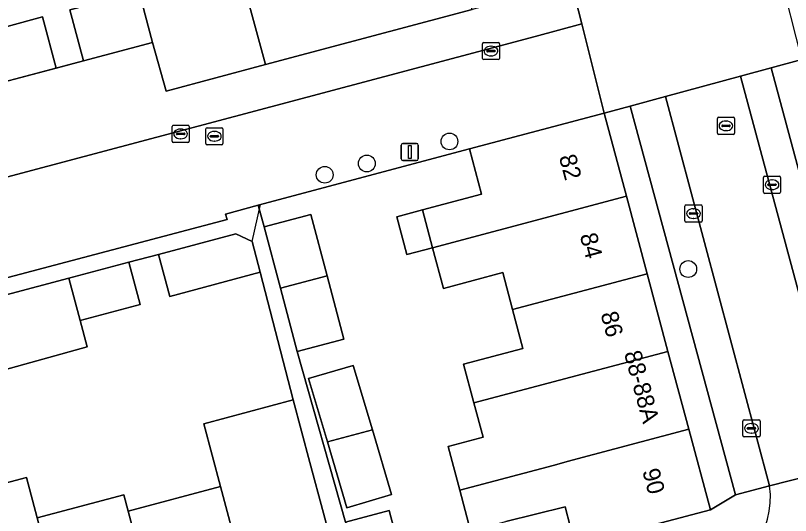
# Model space of a CAD drawing. Extents: x 162542 to 163147, y 380779 to 381521.
# Drawn here: x 162757.65 to 162802.78, y 381070.34 to 381099.45 of the extents above; entities that cross this region are included whole.
import ezdxf

# ---------------------------------------------------------------- set-up
doc = ezdxf.new("R2010")
doc.units = 0
for name, color, linetype in [('IMGEO_Boom', 7, 'Continuous'), ('IMGEO_Erf', 7, 'Continuous'), ('IMGEO_Kolk', 7, 'Continuous'), ('IMGEO_Lichtmast', 7, 'Continuous'), ('IMGEO_Muur', 7, 'Continuous'), ('IMGEO_Pand', 7, 'Continuous'), ('IMGEO_Pand_nummerreeks', 7, 'Continuous'), ('IMGEO_Parkeervlak_open', 7, 'Continuous'), ('IMGEO_Rijbaan_lokaal_open', 7, 'Continuous'), ('IMGEO_Rioolput', 7, 'Continuous'), ('IMGEO_Voetpad_open', 7, 'Continuous')]:
    doc.layers.add(name, color=color, linetype=linetype)

msp = doc.modelspace()

# ---------------------------------------------------------------- linework, layer by layer
at = {"layer": 'IMGEO_Boom'}
for centre in [(162782.921, 381092.117), (162778.113, 381090.832), (162775.658, 381090.177), (162796.83, 381084.688)]:
    msp.add_circle(centre, 0.489, dxfattribs=at)
at = {"layer": 'IMGEO_Erf'}
for points in [[(162755.09, 381098.253), (162759.227, 381099.362), (162760.023, 381096.39), (162761.612, 381096.812), (162760.816, 381099.779), (162764.843, 381100.832), (162763.436, 381106.099), (162757.913, 381104.631), (162752.088, 381103.082)], [(162784.155, 381069.446), (162783.526, 381071.816), (162782.85, 381074.362), (162784.879, 381074.9), (162784.35, 381076.893), (162783.75, 381079.151), (162787.199, 381080.067), (162786.599, 381082.327), (162786.026, 381084.483), (162782.566, 381083.564), (162781.939, 381085.926), (162780.449, 381085.53), (162779.864, 381087.732), (162781.354, 381088.128), (162784.796, 381089.042), (162784.095, 381091.679), (162771.776, 381088.409), (162772.128, 381087.14), (162774.85, 381087.863), (162775.799, 381084.295), (162776.779, 381080.611), (162774.056, 381079.887), (162776.859, 381069.965), (162779.405, 381070.644), (162780.482, 381066.606)], [(162753.086, 381071.17), (162758.292, 381072.559), (162758.919, 381070.209), (162763.957, 381071.553), (162764.213, 381070.599), (162769.584, 381072.032), (162768.611, 381075.681), (162773.82, 381077.07), (162771.904, 381084.512), (162766.629, 381083.09), (162765.973, 381085.543), (162764.247, 381085.085), (162764.909, 381082.626), (162761.423, 381081.687), (162761.823, 381080.162), (162756.645, 381078.719)], [(162790.25, 381068.607), (162789.654, 381070.857), (162786.215, 381069.993)]]:
    msp.add_lwpolyline(points, dxfattribs=at)
for points in [[(162770.633, 381102.367), (162764.843, 381100.832), (162765.622, 381097.877), (162766.422, 381095.044), (162772.214, 381096.585)], [(162778.435, 381075.322), (162779.547, 381071.566), (162776.947, 381070.796), (162775.814, 381074.626), (162774.723, 381078.31), (162777.322, 381079.08)]]:
    msp.add_lwpolyline(points, close=True, dxfattribs=at)
at = {"layer": 'IMGEO_Kolk'}
for p, q in [((162784.841, 381096.951), (162784.841, 381097.803)), ((162784.916, 381097.877), (162785.768, 381097.877)), ((162785.842, 381097.803), (162785.842, 381096.951)), ((162785.1, 381097.371), (162785.1, 381097.383)), ((162785.538, 381097.334), (162785.14, 381097.334)), ((162785.143, 381097.42), (162785.541, 381097.42)), ((162785.329, 381097.657), (162785.354, 381097.657)), ((162785.584, 381097.383), (162785.584, 381097.371)), ((162785.768, 381096.877), (162784.916, 381096.877)), ((162785.352, 381097.097), (162785.327, 381097.097)), ((162766.765, 381092.128), (162766.765, 381092.98)), ((162766.84, 381093.054), (162767.692, 381093.054)), ((162767.253, 381092.834), (162767.278, 381092.834)), ((162767.766, 381092.98), (162767.766, 381092.128)), ((162767.024, 381092.548), (162767.024, 381092.56)), ((162767.462, 381092.511), (162767.064, 381092.511)), ((162767.067, 381092.597), (162767.465, 381092.597)), ((162767.508, 381092.56), (162767.508, 381092.548)), ((162767.692, 381092.054), (162766.84, 381092.054)), ((162767.276, 381092.274), (162767.251, 381092.274)), ((162801.283, 381090.095), (162802.135, 381090.095)), ((162801.208, 381089.169), (162801.208, 381090.021)), ((162801.51, 381089.638), (162801.908, 381089.638)), ((162801.696, 381089.875), (162801.721, 381089.875)), ((162802.209, 381090.021), (162802.209, 381089.169)), ((162801.467, 381089.589), (162801.467, 381089.601)), ((162801.905, 381089.552), (162801.507, 381089.552)), ((162801.719, 381089.315), (162801.694, 381089.315)), ((162801.951, 381089.601), (162801.951, 381089.589)), ((162802.135, 381089.095), (162801.283, 381089.095)), ((162796.635, 381087.492), (162796.635, 381088.344)), ((162796.71, 381088.418), (162797.562, 381088.418)), ((162797.636, 381088.344), (162797.636, 381087.492)), ((162796.894, 381087.912), (162796.894, 381087.924)), ((162797.332, 381087.875), (162796.934, 381087.875)), ((162796.937, 381087.961), (162797.335, 381087.961)), ((162797.123, 381088.198), (162797.148, 381088.198)), ((162797.378, 381087.924), (162797.378, 381087.912)), ((162797.562, 381087.418), (162796.71, 381087.418)), ((162797.146, 381087.638), (162797.121, 381087.638)), ((162800.01, 381074.992), (162800.01, 381075.844)), ((162800.085, 381075.918), (162800.937, 381075.918)), ((162800.498, 381075.698), (162800.523, 381075.698)), ((162801.011, 381075.844), (162801.011, 381074.992)), ((162800.269, 381075.412), (162800.269, 381075.424)), ((162800.707, 381075.375), (162800.309, 381075.375)), ((162800.312, 381075.461), (162800.71, 381075.461)), ((162800.753, 381075.424), (162800.753, 381075.412)), ((162800.937, 381074.918), (162800.085, 381074.918)), ((162800.521, 381075.138), (162800.496, 381075.138))]:
    msp.add_line(p, q, dxfattribs=at)
for points in [[(162784.841, 381096.951), (162784.841, 381097.803)], [(162784.916, 381097.877), (162785.768, 381097.877)], [(162785.842, 381097.803), (162785.842, 381096.951)], [(162785.768, 381096.877), (162784.916, 381096.877)], [(162766.765, 381092.128), (162766.765, 381092.98)], [(162766.84, 381093.054), (162767.692, 381093.054)], [(162767.766, 381092.98), (162767.766, 381092.128)], [(162767.692, 381092.054), (162766.84, 381092.054)], [(162801.283, 381090.095), (162802.135, 381090.095)], [(162801.208, 381089.169), (162801.208, 381090.021)], [(162802.209, 381090.021), (162802.209, 381089.169)], [(162802.135, 381089.095), (162801.283, 381089.095)], [(162796.635, 381087.492), (162796.635, 381088.344)], [(162796.71, 381088.418), (162797.562, 381088.418)], [(162797.636, 381088.344), (162797.636, 381087.492)], [(162797.562, 381087.418), (162796.71, 381087.418)], [(162800.01, 381074.992), (162800.01, 381075.844)], [(162800.085, 381075.918), (162800.937, 381075.918)], [(162801.011, 381075.844), (162801.011, 381074.992)], [(162800.937, 381074.918), (162800.085, 381074.918)]]:
    msp.add_lwpolyline(points, dxfattribs=at)
for centre, radius, start, end in [((162784.918, 381097.801), 0.0765, 91.552, 178.448), ((162784.918, 381097.801), 0.0765, 91.552, 178.448), ((162785.766, 381097.801), 0.0765, 1.552, 88.448), ((162785.766, 381097.801), 0.0765, 1.552, 88.448), ((162785.14, 381097.38), 0.0403, 85.8775, 175.7526), ((162785.137, 381097.37), 0.0366, 178.938, 274.7102), ((162785.541, 381097.377), 0.043, 264.8664, 352.4533), ((162785.545, 381097.382), 0.0386, 1.7309, 96.639), ((162784.918, 381096.953), 0.0765, 181.552, 268.448), ((162784.918, 381096.953), 0.0765, 181.552, 268.448), ((162785.766, 381096.953), 0.0765, 271.552, 358.448), ((162785.766, 381096.953), 0.0765, 271.552, 358.448), ((162766.842, 381092.978), 0.0765, 91.552, 178.448), ((162766.842, 381092.978), 0.0765, 91.552, 178.448), ((162767.69, 381092.978), 0.0765, 1.552, 88.448), ((162767.69, 381092.978), 0.0765, 1.552, 88.448), ((162767.064, 381092.557), 0.0403, 85.8775, 175.7526), ((162767.061, 381092.547), 0.0366, 178.938, 274.7102), ((162767.465, 381092.554), 0.043, 264.8664, 352.4533), ((162767.469, 381092.559), 0.0386, 1.7309, 96.639), ((162766.842, 381092.13), 0.0765, 181.552, 268.448), ((162766.842, 381092.13), 0.0765, 181.552, 268.448), ((162767.69, 381092.13), 0.0765, 271.552, 358.448), ((162767.69, 381092.13), 0.0765, 271.552, 358.448), ((162801.285, 381090.019), 0.0765, 91.552, 178.448), ((162801.285, 381090.019), 0.0765, 91.552, 178.448), ((162802.133, 381090.019), 0.0765, 1.552, 88.448), ((162802.133, 381090.019), 0.0765, 1.552, 88.448), ((162801.507, 381089.598), 0.0403, 85.8775, 175.7526), ((162801.912, 381089.6), 0.0386, 1.7309, 96.639), ((162801.504, 381089.588), 0.0366, 178.938, 274.7102), ((162801.908, 381089.595), 0.043, 264.8664, 352.4533), ((162801.285, 381089.171), 0.0765, 181.552, 268.448), ((162801.285, 381089.171), 0.0765, 181.552, 268.448), ((162802.133, 381089.171), 0.0765, 271.552, 358.448), ((162802.133, 381089.171), 0.0765, 271.552, 358.448), ((162796.712, 381088.342), 0.0765, 91.552, 178.448), ((162796.712, 381088.342), 0.0765, 91.552, 178.448), ((162797.56, 381088.342), 0.0765, 1.552, 88.448), ((162797.56, 381088.342), 0.0765, 1.552, 88.448), ((162796.934, 381087.921), 0.0403, 85.8775, 175.7526), ((162796.931, 381087.911), 0.0366, 178.938, 274.7102), ((162797.335, 381087.918), 0.043, 264.8664, 352.4533), ((162797.339, 381087.923), 0.0386, 1.7309, 96.639), ((162796.712, 381087.494), 0.0765, 181.552, 268.448), ((162796.712, 381087.494), 0.0765, 181.552, 268.448), ((162797.56, 381087.494), 0.0765, 271.552, 358.448), ((162797.56, 381087.494), 0.0765, 271.552, 358.448), ((162800.087, 381075.842), 0.0765, 91.552, 178.448), ((162800.087, 381075.842), 0.0765, 91.552, 178.448), ((162800.935, 381075.842), 0.0765, 1.552, 88.448), ((162800.935, 381075.842), 0.0765, 1.552, 88.448), ((162800.309, 381075.421), 0.0403, 85.8775, 175.7526), ((162800.306, 381075.411), 0.0366, 178.938, 274.7102), ((162800.71, 381075.418), 0.043, 264.8664, 352.4533), ((162800.714, 381075.423), 0.0386, 1.7309, 96.639), ((162800.087, 381074.994), 0.0765, 181.552, 268.448), ((162800.087, 381074.994), 0.0765, 181.552, 268.448), ((162800.935, 381074.994), 0.0765, 271.552, 358.448), ((162800.935, 381074.994), 0.0765, 271.552, 358.448)]:
    msp.add_arc(centre, radius, start, end, dxfattribs=at)
for centre, major_axis, ratio, start_param, end_param in [((162785.328, 381097.377), (-0.387, 0.002), 0.722429, 4.712389, 7.853982), ((162785.353, 381097.377), (-0.39, 0.002), 0.717154, 1.570796, 4.712389), ((162767.252, 381092.554), (-0.387, 0.002), 0.722429, 4.712389, 7.853982), ((162767.277, 381092.554), (-0.39, 0.002), 0.717154, 1.570796, 4.712389), ((162801.695, 381089.595), (-0.387, 0.002), 0.722429, 4.712389, 7.853982), ((162801.72, 381089.595), (-0.39, 0.002), 0.717154, 1.570796, 4.712389), ((162797.122, 381087.918), (-0.387, 0.002), 0.722429, 4.712389, 7.853982), ((162797.147, 381087.918), (-0.39, 0.002), 0.717154, 1.570796, 4.712389), ((162800.497, 381075.418), (-0.387, 0.002), 0.722429, 4.712389, 7.853982), ((162800.522, 381075.418), (-0.39, 0.002), 0.717154, 1.570796, 4.712389)]:
    msp.add_ellipse(centre, major_axis=major_axis, ratio=ratio, start_param=start_param, end_param=end_param, dxfattribs=at)
at = {"layer": 'IMGEO_Lichtmast'}
for p, q in [((162780.113, 381091.106), (162780.113, 381091.906)), ((162780.113, 381091.906), (162780.113, 381091.106)), ((162780.213, 381092.006), (162781.003, 381092.006)), ((162781.003, 381092.006), (162780.213, 381092.006)), ((162781.103, 381091.906), (162781.103, 381091.106)), ((162781.103, 381091.106), (162781.103, 381091.906)), ((162781.003, 381091.006), (162780.213, 381091.006)), ((162780.213, 381091.006), (162781.003, 381091.006))]:
    msp.add_line(p, q, dxfattribs=at)
msp.add_lwpolyline([(162780.533, 381091.881), (162780.683, 381091.881), (162780.683, 381091.131), (162780.533, 381091.131), (162780.533, 381091.881)], dxfattribs=at)
for centre, start, end in [((162780.213, 381091.906), 90, 180), ((162780.213, 381091.906), 90, 180), ((162781.003, 381091.906), 0, 90), ((162781.003, 381091.906), 360, 90), ((162780.213, 381091.106), 180, 270), ((162780.213, 381091.106), 180, 270), ((162781.003, 381091.106), 270, 0), ((162781.003, 381091.106), 270, 0)]:
    msp.add_arc(centre, 0.1, start, end, dxfattribs=at)
at = {"layer": 'IMGEO_Muur'}
for points in [[(162772.214, 381096.585), (162766.422, 381095.044), (162765.622, 381097.877), (162701.846, 381080.936)], [(162771.921, 381088.449), (162784.095, 381091.679)], [(162771.43, 381086.295), (162771.921, 381088.449)]]:
    msp.add_lwpolyline(points, dxfattribs=at)
at = {"layer": 'IMGEO_Pand'}
for points in [[(162763.436, 381106.099), (162764.843, 381100.832), (162770.633, 381102.367), (162772.214, 381096.585), (162784.24, 381099.787), (162782.711, 381105.584), (162788.487, 381107.117), (162785.291, 381119.142), (162779.493, 381117.608), (162777.951, 381123.405), (162765.901, 381120.189), (162767.441, 381114.419), (162761.884, 381112.936)], [(162764.843, 381100.832), (162760.816, 381099.779), (162761.612, 381096.812), (162765.622, 381097.877)], [(162759.227, 381099.362), (162755.09, 381098.253), (162755.884, 381095.29), (162760.023, 381096.39)], [(162793.225, 381088.924), (162791.929, 381093.758), (162784.095, 381091.679), (162784.796, 381089.042), (162781.354, 381088.128), (162781.939, 381085.926)], [(162794.436, 381084.409), (162793.225, 381088.924), (162781.939, 381085.926), (162782.566, 381083.564), (162786.026, 381084.483), (162786.599, 381082.327)], [(162772.128, 381087.14), (162773.076, 381083.572), (162775.799, 381084.295), (162774.85, 381087.863)], [(162781.354, 381088.128), (162779.864, 381087.732), (162780.449, 381085.53), (162781.939, 381085.926)], [(162765.973, 381085.543), (162766.629, 381083.09), (162771.904, 381084.512), (162771.43, 381086.295), (162770.479, 381086.739)], [(162764.247, 381085.085), (162760.765, 381084.161), (162761.423, 381081.687), (162764.909, 381082.626)], [(162775.799, 381084.295), (162773.076, 381083.572), (162774.056, 381079.887), (162776.779, 381080.611)], [(162795.646, 381079.894), (162794.436, 381084.409), (162786.599, 381082.327), (162787.199, 381080.067), (162783.75, 381079.151), (162784.35, 381076.893)], [(162755.559, 381082.78), (162756.645, 381078.719), (162761.823, 381080.162), (162761.423, 381081.687), (162760.765, 381084.161)], [(162795.646, 381079.894), (162784.35, 381076.893), (162784.879, 381074.9), (162782.85, 381074.362), (162783.526, 381071.816), (162788.962, 381073.26), (162789.181, 381073.318), (162789.775, 381073.478), (162796.857, 381075.377)], [(162775.814, 381074.626), (162778.435, 381075.322), (162777.322, 381079.08), (162774.723, 381078.31)], [(162771.805, 381063.723), (162774.182, 381064.357), (162774.346, 381064.969), (162776.867, 381065.641), (162775.579, 381070.473), (162774.793, 381073.421), (162773.82, 381077.07), (162768.611, 381075.681), (162769.584, 381072.032)], [(162775.814, 381074.626), (162776.947, 381070.796), (162779.547, 381071.566), (162778.435, 381075.322)], [(162796.857, 381075.377), (162789.775, 381073.478), (162789.181, 381073.318), (162788.962, 381073.26), (162783.526, 381071.816), (162784.155, 381069.446), (162786.215, 381069.993), (162789.654, 381070.857), (162790.25, 381068.607), (162798.117, 381070.679)], [(162753.086, 381071.17), (162755.78, 381061.091), (162758.026, 381061.69), (162758.49, 381061.225), (162761.132, 381061.93), (162758.919, 381070.209), (162758.292, 381072.559)], [(162769.584, 381072.032), (162764.213, 381070.599), (162766.025, 381063.843), (162765.878, 381063.804), (162766.136, 381062.838), (162768.598, 381063.494), (162769.091, 381063), (162771.805, 381063.723)], [(162764.213, 381070.599), (162763.957, 381071.553), (162758.919, 381070.209), (162761.132, 381061.93), (162763.577, 381062.582), (162763.754, 381063.237), (162765.878, 381063.804), (162766.025, 381063.843)], [(162780.482, 381066.606), (162779.405, 381070.644), (162776.859, 381069.965), (162777.935, 381065.927)]]:
    msp.add_lwpolyline(points, close=True, dxfattribs=at)
at = {"layer": 'IMGEO_Parkeervlak_open'}
for points in [[(162801.665, 381096.397), (162799.877, 381095.912), (162805.992, 381073.201), (162807.774, 381073.68)], [(162795.495, 381094.724), (162793.451, 381094.17), (162799.581, 381071.542), (162801.57, 381072.075)]]:
    msp.add_lwpolyline(points, close=True, dxfattribs=at)
at = {"layer": 'IMGEO_Rijbaan_lokaal_open'}
for points in [[(162786.828, 381126.404), (162786.99, 381125.797), (162793.293, 381102.208), (162791.494, 381101.727), (162790.033, 381101.331), (162790.628, 381098.953), (162791.929, 381093.758), (162793.451, 381094.17), (162795.495, 381094.724), (162799.877, 381095.912), (162801.665, 381096.397), (162803.453, 381096.881), (162802.147, 381102.023), (162800.34, 381101.542), (162799.714, 381103.9), (162797.792, 381103.41), (162791.52, 381126.983)], [(162805.992, 381073.201), (162801.57, 381072.075)]]:
    msp.add_lwpolyline(points, dxfattribs=at)
for points in [[(162769.976, 381087.575), (162769.876, 381087.879), (162771.776, 381088.409), (162784.095, 381091.679), (162791.929, 381093.758), (162790.628, 381098.953), (162787.911, 381098.229), (162654.159, 381062.654), (162655.028, 381059.467), (162655.628, 381057.268), (162655.725, 381057.293), (162692.811, 381067.153), (162695.634, 381067.905), (162698.168, 381068.579), (162700.7, 381069.254), (162703.311, 381069.95)], [(162799.877, 381095.912), (162795.495, 381094.724), (162801.57, 381072.075), (162805.992, 381073.201)]]:
    msp.add_lwpolyline(points, close=True, dxfattribs=at)
msp.add_arc((162796.373, 381071.413), 5.239, 282.7716, 7.263, dxfattribs=at)
at = {"layer": 'IMGEO_Rioolput'}
for p, q in [((162798.525, 381092.599), (162798.525, 381093.451)), ((162798.6, 381093.525), (162799.452, 381093.525)), ((162799.013, 381093.305), (162799.038, 381093.305)), ((162799.526, 381093.451), (162799.526, 381092.599)), ((162768.732, 381091.991), (162768.732, 381092.843)), ((162768.807, 381092.917), (162769.659, 381092.917)), ((162769.733, 381092.843), (162769.733, 381091.991)), ((162798.784, 381093.019), (162798.784, 381093.031)), ((162799.222, 381092.982), (162798.824, 381092.982)), ((162798.827, 381093.068), (162799.225, 381093.068)), ((162799.268, 381093.031), (162799.268, 381093.019)), ((162768.991, 381092.411), (162768.991, 381092.423)), ((162769.429, 381092.374), (162769.031, 381092.374)), ((162769.034, 381092.46), (162769.432, 381092.46)), ((162769.22, 381092.697), (162769.245, 381092.697)), ((162769.475, 381092.423), (162769.475, 381092.411)), ((162799.452, 381092.525), (162798.6, 381092.525)), ((162799.036, 381092.745), (162799.011, 381092.745)), ((162769.659, 381091.917), (162768.807, 381091.917)), ((162769.243, 381092.137), (162769.218, 381092.137))]:
    msp.add_line(p, q, dxfattribs=at)
for points in [[(162798.525, 381092.599), (162798.525, 381093.451)], [(162798.6, 381093.525), (162799.452, 381093.525)], [(162799.526, 381093.451), (162799.526, 381092.599)], [(162768.732, 381091.991), (162768.732, 381092.843)], [(162768.807, 381092.917), (162769.659, 381092.917)], [(162769.733, 381092.843), (162769.733, 381091.991)], [(162799.452, 381092.525), (162798.6, 381092.525)], [(162769.659, 381091.917), (162768.807, 381091.917)]]:
    msp.add_lwpolyline(points, dxfattribs=at)
for centre, radius, start, end in [((162798.602, 381093.449), 0.0765, 91.552, 178.448), ((162798.602, 381093.449), 0.0765, 91.552, 178.448), ((162799.45, 381093.449), 0.0765, 1.552, 88.448), ((162799.45, 381093.449), 0.0765, 1.552, 88.448), ((162768.809, 381092.841), 0.0765, 91.552, 178.448), ((162768.809, 381092.841), 0.0765, 91.552, 178.448), ((162769.657, 381092.841), 0.0765, 1.552, 88.448), ((162769.657, 381092.841), 0.0765, 1.552, 88.448), ((162798.824, 381093.028), 0.0403, 85.8775, 175.7526), ((162798.821, 381093.018), 0.0366, 178.938, 274.7102), ((162799.225, 381093.025), 0.043, 264.8664, 352.4533), ((162799.229, 381093.03), 0.0386, 1.7309, 96.639), ((162769.031, 381092.42), 0.0403, 85.8775, 175.7526), ((162769.028, 381092.41), 0.0366, 178.938, 274.7102), ((162769.432, 381092.417), 0.043, 264.8664, 352.4533), ((162769.436, 381092.422), 0.0386, 1.7309, 96.639), ((162798.602, 381092.601), 0.0765, 181.552, 268.448), ((162798.602, 381092.601), 0.0765, 181.552, 268.448), ((162799.45, 381092.601), 0.0765, 271.552, 358.448), ((162799.45, 381092.601), 0.0765, 271.552, 358.448), ((162768.809, 381091.993), 0.0765, 181.552, 268.448), ((162768.809, 381091.993), 0.0765, 181.552, 268.448), ((162769.657, 381091.993), 0.0765, 271.552, 358.448), ((162769.657, 381091.993), 0.0765, 271.552, 358.448)]:
    msp.add_arc(centre, radius, start, end, dxfattribs=at)
for centre, major_axis, ratio, start_param, end_param in [((162799.012, 381093.025), (-0.387, 0.002), 0.722429, 4.712389, 7.853982), ((162799.037, 381093.025), (-0.39, 0.002), 0.717154, 1.570796, 4.712389), ((162769.219, 381092.417), (-0.387, 0.002), 0.722429, 4.712389, 7.853982), ((162769.244, 381092.417), (-0.39, 0.002), 0.717154, 1.570796, 4.712389)]:
    msp.add_ellipse(centre, major_axis=major_axis, ratio=ratio, start_param=start_param, end_param=end_param, dxfattribs=at)
at = {"layer": 'IMGEO_Voetpad_open'}
for points in [[(162654.159, 381062.654), (162787.911, 381098.229), (162790.628, 381098.953), (162790.033, 381101.331), (162784.24, 381099.787), (162772.214, 381096.585), (162766.422, 381095.044), (162765.622, 381097.877), (162761.612, 381096.812), (162760.023, 381096.39), (162755.884, 381095.29)], [(162776.859, 381069.965), (162774.056, 381079.887), (162773.076, 381083.572), (162772.128, 381087.14), (162771.776, 381088.409), (162769.876, 381087.879), (162769.976, 381087.575), (162703.311, 381069.95)], [(162708.711, 381070.294), (162712.292, 381071.3), (162715.625, 381072.185), (162719.111, 381073.11), (162722.642, 381074.047), (162726.075, 381074.957), (162729.524, 381075.872), (162732.998, 381076.794), (162734.704, 381077.247), (162739.938, 381078.636), (162743.478, 381079.575), (162746.612, 381080.406), (162750.352, 381081.399), (162755.559, 381082.78), (162760.765, 381084.161), (162764.247, 381085.085), (162765.973, 381085.543), (162770.479, 381086.739), (162771.43, 381086.295), (162771.904, 381084.512), (162773.82, 381077.07), (162774.793, 381073.421), (162775.579, 381070.473), (162776.867, 381065.641)], [(162801.57, 381072.075), (162799.581, 381071.542), (162798.117, 381070.679), (162790.25, 381068.607)]]:
    msp.add_lwpolyline(points, dxfattribs=at)
for points in [[(162807.239, 381082.782), (162806.02, 381087.321), (162804.809, 381091.832), (162803.453, 381096.881), (162801.665, 381096.397), (162807.774, 381073.68), (162809.671, 381073.727), (162808.428, 381078.354)], [(162793.451, 381094.17), (162791.929, 381093.758), (162793.225, 381088.924), (162794.436, 381084.409), (162795.646, 381079.894), (162796.857, 381075.377), (162798.117, 381070.679), (162799.581, 381071.542)]]:
    msp.add_lwpolyline(points, close=True, dxfattribs=at)
msp.add_arc((162796.373, 381071.413), 5.239, 282.7716, 7.263, dxfattribs=at)

# ---------------------------------------------------------------- texts
at = {"layer": 'IMGEO_Pand_nummerreeks'}
for s, rotation, p in [('82', 284.8693, (162789.291, 381091.222)), ('84', 284.8693, (162790.505, 381086.65)), ('86', 284.8693, (162791.718, 381082.08)), ('88-88A', 285.0056, (162793.082, 381079.8)), ('90', 284.868, (162794.146, 381072.939))]:
    msp.add_text(s, height=1, rotation=rotation, dxfattribs=at).set_placement(p)

doc.saveas('drawing.dxf')
